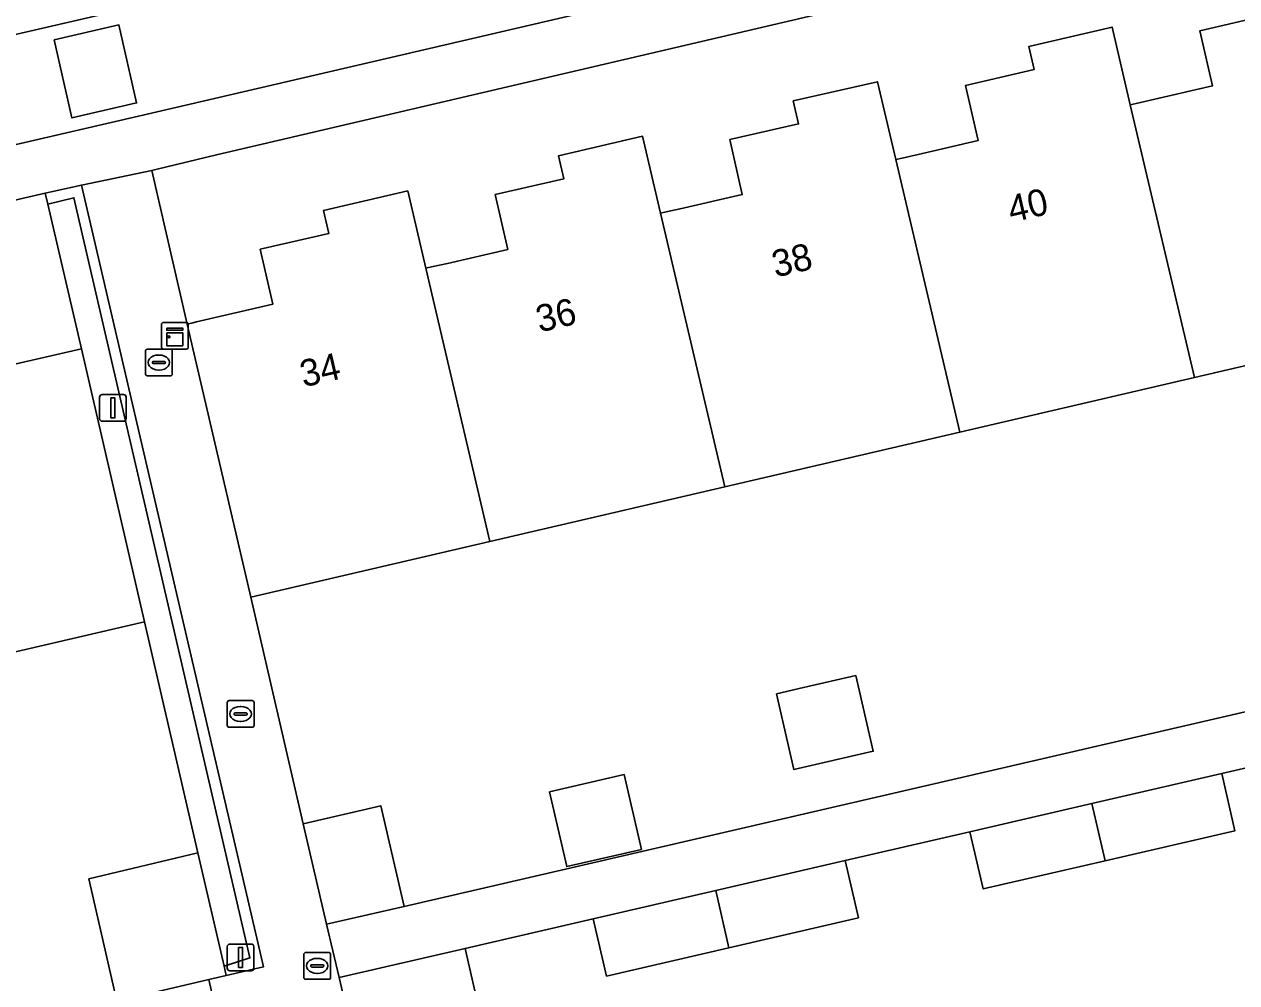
# Model space of a CAD drawing. Extents: x 156412 to 157779, y 382335 to 383768.
# Drawn here: x 156851.95 to 156897.2, y 382800.53 to 382836.3 of the extents above; entities that cross this region are included whole.
import ezdxf

# ---------------------------------------------------------------- set-up
doc = ezdxf.new("R2010")
doc.units = 0
for name, color, linetype in [('IMGEO_Erf', 7, 'Continuous'), ('IMGEO_Groenvoorziening', 7, 'Continuous'), ('IMGEO_Kast', 7, 'Continuous'), ('IMGEO_Kolk', 7, 'Continuous'), ('IMGEO_Lichtmast', 7, 'Continuous'), ('IMGEO_Muur', 7, 'Continuous'), ('IMGEO_Pand', 7, 'Continuous'), ('IMGEO_Pand_nummerreeks', 7, 'Continuous'), ('IMGEO_Rijbaan_lokaal_gesloten', 7, 'Continuous'), ('IMGEO_Rijbaan_lokaal_open', 7, 'Continuous'), ('IMGEO_Rioolput', 7, 'Continuous'), ('IMGEO_Voetpad_open', 7, 'Continuous')]:
    doc.layers.add(name, color=color, linetype=linetype)

msp = doc.modelspace()

# ---------------------------------------------------------------- linework, layer by layer
at = {"layer": 'IMGEO_Erf'}
for points in [[(156927.114, 382847.315), (156859.126, 382831.425), (156856.91, 382830.891), (156856.714, 382830.844), (156858.03, 382825.104), (156858.233, 382825.158), (156858.381, 382825.198), (156861.226, 382825.856), (156860.753, 382827.902), (156863.315, 382828.495), (156863.117, 382829.352), (156866.258, 382830.078), (156866.935, 382827.191), (156867.151, 382827.241), (156867.738, 382827.376), (156869.996, 382827.897), (156869.524, 382829.944), (156872.086, 382830.535), (156871.889, 382831.393), (156875.024, 382832.117), (156875.698, 382829.25), (156875.9, 382829.296), (156876.422, 382829.415), (156878.747, 382829.944), (156878.28, 382831.992), (156880.845, 382832.576), (156880.649, 382833.434), (156883.79, 382834.15), (156884.473, 382831.247), (156884.71, 382831.302), (156885.471, 382831.48), (156887.553, 382831.965), (156887.077, 382834.01), (156889.638, 382834.608), (156889.438, 382835.465), (156892.545, 382836.189), (156893.227, 382833.293), (156893.451, 382833.345), (156894.3, 382833.542), (156896.296, 382834.004), (156895.822, 382836.05), (156898.385, 382836.643)], [(156850.878, 382823.45), (156854.088, 382824.184), (156852.823, 382829.586), (156852.727, 382829.996), (156782.34, 382813.73)], [(156901.237, 382809.4), (156896.638, 382808.337), (156897.131, 382806.203), (156892.289, 382805.084), (156887.738, 382804.033), (156887.245, 382806.167), (156882.588, 382805.091), (156883.082, 382802.956), (156878.25, 382801.84), (156873.679, 382800.784), (156873.186, 382802.919), (156868.402, 382801.813), (156868.894, 382799.682)]]:
    msp.add_lwpolyline(points, dxfattribs=at)
for points in [[(156923.79, 382820.948), (156926.665, 382821.615), (156927.6, 382817.588), (156933.697, 382818.983), (156930.84, 382831.306), (156921.915, 382829.231), (156913.155, 382827.194), (156913.44, 382825.7), (156908.457, 382824.541), (156908.113, 382826.021), (156904.385, 382825.154), (156895.625, 382823.117), (156886.866, 382821.08), (156878.096, 382819.04), (156869.326, 382817.001), (156860.401, 382814.925), (156862.355, 382806.461), (156865.257, 382807.132), (156866.124, 382803.38), (156910.089, 382813.546), (156924.725, 382816.92)], [(156854.352, 382804.41), (156858.429, 382805.383), (156856.435, 382813.996), (156847.542, 382811.941), (156838.763, 382809.913), (156830.005, 382807.89), (156821.243, 382805.866), (156812.469, 382803.839), (156803.704, 382801.814), (156794.934, 382799.788), (156786.03, 382797.749), (156789.002, 382784.941), (156789.092, 382784.551), (156855.404, 382799.852)], [(156880.02, 382811.313), (156881.026, 382811.545), (156882.978, 382811.996), (156883.631, 382809.171), (156880.672, 382808.488)], [(156871.551, 382807.654), (156874.339, 382808.298), (156874.983, 382805.51), (156872.195, 382804.867)]]:
    msp.add_lwpolyline(points, close=True, dxfattribs=at)
at = {"layer": 'IMGEO_Groenvoorziening'}
msp.add_lwpolyline([(156859.404, 382801.15), (156860.37, 382801.457), (156853.8, 382829.822), (156852.823, 382829.586), (156854.088, 382824.184), (156856.435, 382813.996), (156858.429, 382805.383)], close=True, dxfattribs=at)
at = {"layer": 'IMGEO_Kast'}
for p, q in [((156857.069, 382824.248), (156857.069, 382825.089)), ((156857.069, 382825.089), (156857.069, 382824.248)), ((156857.144, 382825.173), (156857.985, 382825.173)), ((156857.985, 382825.173), (156857.144, 382825.173)), ((156858.069, 382825.098), (156858.069, 382824.257)), ((156858.069, 382824.257), (156858.069, 382825.098)), ((156857.994, 382824.173), (156857.153, 382824.173)), ((156857.153, 382824.173), (156857.994, 382824.173))]:
    msp.add_line(p, q, dxfattribs=at)
for points in [[(156857.264, 382824.963), (156857.864, 382824.963), (156857.864, 382824.878), (156857.264, 382824.878), (156857.264, 382824.963)], [(156857.264, 382824.788), (156857.864, 382824.788), (156857.864, 382824.299), (156857.264, 382824.299), (156857.264, 382824.788)]]:
    msp.add_lwpolyline(points, dxfattribs=at)
msp.add_circle((156857.348, 382824.637), 0.0377, dxfattribs=at)
for centre, start, end in [((156857.147, 382825.095), 92.4484, 184.2845), ((156857.147, 382825.095), 92.4484, 184.2845), ((156857.991, 382825.095), 2.4484, 94.2845), ((156857.991, 382825.095), 2.4484, 94.2845), ((156857.147, 382824.251), 182.4484, 274.2845), ((156857.147, 382824.251), 182.4484, 274.2845), ((156857.991, 382824.251), 272.4484, 4.2845), ((156857.991, 382824.251), 272.4484, 4.2845)]:
    msp.add_arc(centre, 0.0779, start, end, dxfattribs=at)
at = {"layer": 'IMGEO_Kolk'}
for p, q in [((156856.47, 382823.25), (156856.47, 382824.102)), ((156856.545, 382824.176), (156857.397, 382824.176)), ((156856.958, 382823.956), (156856.983, 382823.956)), ((156857.471, 382824.102), (156857.471, 382823.25)), ((156856.729, 382823.67), (156856.729, 382823.682)), ((156857.167, 382823.633), (156856.769, 382823.633)), ((156856.772, 382823.719), (156857.17, 382823.719)), ((156857.213, 382823.682), (156857.213, 382823.67)), ((156857.397, 382823.176), (156856.545, 382823.176)), ((156856.981, 382823.396), (156856.956, 382823.396)), ((156859.522, 382810.138), (156859.522, 382810.99)), ((156859.597, 382811.064), (156860.449, 382811.064)), ((156860.01, 382810.844), (156860.035, 382810.844)), ((156860.523, 382810.99), (156860.523, 382810.138)), ((156859.781, 382810.558), (156859.781, 382810.57)), ((156860.219, 382810.521), (156859.821, 382810.521)), ((156859.824, 382810.607), (156860.222, 382810.607)), ((156860.265, 382810.57), (156860.265, 382810.558)), ((156860.449, 382810.064), (156859.597, 382810.064)), ((156860.033, 382810.284), (156860.008, 382810.284))]:
    msp.add_line(p, q, dxfattribs=at)
for points in [[(156856.47, 382823.25), (156856.47, 382824.102)], [(156856.545, 382824.176), (156857.397, 382824.176)], [(156857.471, 382824.102), (156857.471, 382823.25)], [(156857.397, 382823.176), (156856.545, 382823.176)], [(156859.522, 382810.138), (156859.522, 382810.99)], [(156859.597, 382811.064), (156860.449, 382811.064)], [(156860.523, 382810.99), (156860.523, 382810.138)], [(156860.449, 382810.064), (156859.597, 382810.064)]]:
    msp.add_lwpolyline(points, dxfattribs=at)
for centre, radius, start, end in [((156856.547, 382824.1), 0.0765, 91.552, 178.448), ((156856.547, 382824.1), 0.0765, 91.552, 178.448), ((156857.395, 382824.1), 0.0765, 1.552, 88.448), ((156857.395, 382824.1), 0.0765, 1.552, 88.448), ((156856.769, 382823.679), 0.0403, 85.8775, 175.7526), ((156856.766, 382823.669), 0.0366, 178.938, 274.7102), ((156857.17, 382823.676), 0.043, 264.8664, 352.4533), ((156857.174, 382823.681), 0.0386, 1.7309, 96.639), ((156856.547, 382823.252), 0.0765, 181.552, 268.448), ((156856.547, 382823.252), 0.0765, 181.552, 268.448), ((156857.395, 382823.252), 0.0765, 271.552, 358.448), ((156857.395, 382823.252), 0.0765, 271.552, 358.448), ((156859.599, 382810.988), 0.0765, 91.552, 178.448), ((156859.599, 382810.988), 0.0765, 91.552, 178.448), ((156860.447, 382810.988), 0.0765, 1.552, 88.448), ((156860.447, 382810.988), 0.0765, 1.552, 88.448), ((156859.821, 382810.567), 0.0403, 85.8775, 175.7526), ((156859.818, 382810.557), 0.0366, 178.938, 274.7102), ((156860.222, 382810.564), 0.043, 264.8664, 352.4533), ((156860.226, 382810.569), 0.0386, 1.7309, 96.639), ((156859.599, 382810.14), 0.0765, 181.552, 268.448), ((156859.599, 382810.14), 0.0765, 181.552, 268.448), ((156860.447, 382810.14), 0.0765, 271.552, 358.448), ((156860.447, 382810.14), 0.0765, 271.552, 358.448)]:
    msp.add_arc(centre, radius, start, end, dxfattribs=at)
for centre, major_axis, ratio, start_param, end_param in [((156856.957, 382823.676), (-0.387, 0.002), 0.722429, 4.712389, 7.853982), ((156856.982, 382823.676), (-0.39, 0.002), 0.717154, 1.570796, 4.712389), ((156860.009, 382810.564), (-0.387, 0.002), 0.722429, 4.712389, 7.853982), ((156860.034, 382810.564), (-0.39, 0.002), 0.717154, 1.570796, 4.712389)]:
    msp.add_ellipse(centre, major_axis=major_axis, ratio=ratio, start_param=start_param, end_param=end_param, dxfattribs=at)
at = {"layer": 'IMGEO_Lichtmast'}
for p, q in [((156854.761, 382821.582), (156854.761, 382822.382)), ((156854.761, 382822.382), (156854.761, 382821.582)), ((156854.861, 382822.482), (156855.651, 382822.482)), ((156855.651, 382822.482), (156854.861, 382822.482)), ((156855.751, 382822.382), (156855.751, 382821.582)), ((156855.751, 382821.582), (156855.751, 382822.382)), ((156855.651, 382821.482), (156854.861, 382821.482)), ((156854.861, 382821.482), (156855.651, 382821.482)), ((156859.525, 382801.079), (156859.525, 382801.879)), ((156859.525, 382801.879), (156859.525, 382801.079)), ((156859.625, 382801.979), (156860.415, 382801.979)), ((156860.415, 382801.979), (156859.625, 382801.979)), ((156860.515, 382801.879), (156860.515, 382801.079)), ((156860.515, 382801.079), (156860.515, 382801.879)), ((156860.415, 382800.979), (156859.625, 382800.979)), ((156859.625, 382800.979), (156860.415, 382800.979))]:
    msp.add_line(p, q, dxfattribs=at)
for points in [[(156855.181, 382822.357), (156855.331, 382822.357), (156855.331, 382821.607), (156855.181, 382821.607), (156855.181, 382822.357)], [(156859.945, 382801.854), (156860.095, 382801.854), (156860.095, 382801.104), (156859.945, 382801.104), (156859.945, 382801.854)]]:
    msp.add_lwpolyline(points, dxfattribs=at)
for centre, start, end in [((156854.861, 382822.382), 90, 180), ((156854.861, 382822.382), 90, 180), ((156855.651, 382822.382), 0, 90), ((156855.651, 382822.382), 360, 90), ((156854.861, 382821.582), 180, 270), ((156854.861, 382821.582), 180, 270), ((156855.651, 382821.582), 270, 0), ((156855.651, 382821.582), 270, 0), ((156859.625, 382801.879), 90, 180), ((156859.625, 382801.879), 90, 180), ((156860.415, 382801.879), 0, 90), ((156860.415, 382801.879), 360, 90), ((156859.625, 382801.079), 180, 270), ((156859.625, 382801.079), 180, 270), ((156860.415, 382801.079), 270, 0), ((156860.415, 382801.079), 270, 0)]:
    msp.add_arc(centre, 0.1, start, end, dxfattribs=at)
at = {"layer": 'IMGEO_Muur'}
msp.add_lwpolyline([(156854.08, 382830.294), (156852.727, 382829.996), (156852.823, 382829.586), (156853.8, 382829.822), (156860.37, 382801.457), (156859.404, 382801.15), (156859.483, 382800.805), (156860.871, 382801.126)], close=True, dxfattribs=at)
for points in [[(156862.355, 382806.461), (156860.401, 382814.925)], [(156856.435, 382813.996), (156858.429, 382805.383)]]:
    msp.add_lwpolyline(points, dxfattribs=at)
at = {"layer": 'IMGEO_Pand'}
for points in [[(156901.988, 382835.311), (156901.301, 382838.221), (156898.186, 382837.5), (156898.385, 382836.643), (156895.822, 382836.05), (156896.296, 382834.004), (156894.3, 382833.542), (156893.451, 382833.345), (156893.227, 382833.293), (156895.625, 382823.117), (156904.385, 382825.154)], [(156893.227, 382833.293), (156892.545, 382836.189), (156889.438, 382835.465), (156889.638, 382834.608), (156887.077, 382834.01), (156887.553, 382831.965), (156885.471, 382831.48), (156884.71, 382831.302), (156884.473, 382831.247), (156886.866, 382821.08), (156895.625, 382823.117)], [(156884.473, 382831.247), (156883.79, 382834.15), (156880.649, 382833.434), (156880.845, 382832.576), (156878.28, 382831.992), (156878.747, 382829.944), (156876.422, 382829.415), (156875.9, 382829.296), (156875.698, 382829.25), (156878.096, 382819.04), (156886.866, 382821.08)], [(156875.698, 382829.25), (156875.024, 382832.117), (156871.889, 382831.393), (156872.086, 382830.535), (156869.524, 382829.944), (156869.996, 382827.897), (156867.738, 382827.376), (156867.151, 382827.241), (156866.935, 382827.191), (156869.326, 382817.001), (156878.096, 382819.04)], [(156866.935, 382827.191), (156866.258, 382830.078), (156863.117, 382829.352), (156863.315, 382828.495), (156860.753, 382827.902), (156861.226, 382825.856), (156858.381, 382825.198), (156858.233, 382825.158), (156858.03, 382825.104), (156860.401, 382814.925), (156869.326, 382817.001)], [(156844.51, 382825.019), (156847.542, 382811.941), (156856.435, 382813.996), (156854.088, 382824.184), (156850.878, 382823.45), (156850.4, 382825.479), (156847.859, 382824.88), (156847.662, 382825.748)], [(156880.02, 382811.313), (156880.672, 382808.488), (156883.631, 382809.171), (156882.978, 382811.996), (156881.026, 382811.545)], [(156871.551, 382807.654), (156872.195, 382804.867), (156874.983, 382805.51), (156874.339, 382808.298)], [(156892.289, 382805.084), (156897.131, 382806.203), (156896.638, 382808.337), (156891.793, 382807.218)], [(156892.289, 382805.084), (156891.793, 382807.218), (156887.245, 382806.167), (156887.738, 382804.033)], [(156862.355, 382806.461), (156863.234, 382802.713), (156866.124, 382803.38), (156865.257, 382807.132)], [(156859.404, 382801.15), (156858.429, 382805.383), (156854.352, 382804.41), (156855.404, 382799.852), (156858.834, 382800.653), (156859.483, 382800.805)], [(156878.25, 382801.84), (156883.082, 382802.956), (156882.588, 382805.091), (156877.753, 382803.974)], [(156878.25, 382801.84), (156877.753, 382803.974), (156873.186, 382802.919), (156873.679, 382800.784)], [(156863.704, 382800.728), (156864.203, 382798.597), (156868.894, 382799.682), (156868.402, 382801.813)]]:
    msp.add_lwpolyline(points, close=True, dxfattribs=at)
at = {"layer": 'IMGEO_Rijbaan_lokaal_gesloten'}
for points in [[(156925.817, 382853.068), (156855.39, 382836.785), (156816.178, 382827.739), (156776.982, 382818.697), (156706.623, 382802.451), (156704.67, 382802.003), (156705.372, 382798.026), (156707.336, 382798.509), (156707.464, 382798.538), (156780.281, 382815.295), (156817.084, 382823.811), (156856.378, 382832.904)], [(156856.378, 382832.904), (156923.197, 382848.454), (156926.664, 382849.268), (156926.769, 382849.293)]]:
    msp.add_lwpolyline(points, dxfattribs=at)
msp.add_lwpolyline([(156853.064, 382835.711), (156855.479, 382836.274), (156856.141, 382833.365), (156853.725, 382832.8)], close=True, dxfattribs=at)
at = {"layer": 'IMGEO_Rijbaan_lokaal_open'}
msp.add_lwpolyline([(156704.67, 382802.003), (156706.623, 382802.451), (156776.982, 382818.697), (156816.178, 382827.739), (156855.39, 382836.785), (156925.817, 382853.068)], dxfattribs=at)
msp.add_lwpolyline([(156853.725, 382832.8), (156856.141, 382833.365), (156855.479, 382836.274), (156853.064, 382835.711)], close=True, dxfattribs=at)
at = {"layer": 'IMGEO_Rioolput'}
for p, q in [((156862.381, 382800.737), (156862.381, 382801.589)), ((156862.456, 382801.663), (156863.308, 382801.663)), ((156862.869, 382801.443), (156862.894, 382801.443)), ((156863.382, 382801.589), (156863.382, 382800.737)), ((156862.64, 382801.157), (156862.64, 382801.169)), ((156863.078, 382801.12), (156862.68, 382801.12)), ((156862.683, 382801.206), (156863.081, 382801.206)), ((156862.892, 382800.883), (156862.867, 382800.883)), ((156863.124, 382801.169), (156863.124, 382801.157)), ((156863.308, 382800.663), (156862.456, 382800.663))]:
    msp.add_line(p, q, dxfattribs=at)
for points in [[(156862.381, 382800.737), (156862.381, 382801.589)], [(156862.456, 382801.663), (156863.308, 382801.663)], [(156863.382, 382801.589), (156863.382, 382800.737)], [(156863.308, 382800.663), (156862.456, 382800.663)]]:
    msp.add_lwpolyline(points, dxfattribs=at)
for centre, radius, start, end in [((156862.458, 382801.587), 0.0765, 91.552, 178.448), ((156862.458, 382801.587), 0.0765, 91.552, 178.448), ((156863.306, 382801.587), 0.0765, 1.552, 88.448), ((156863.306, 382801.587), 0.0765, 1.552, 88.448), ((156862.68, 382801.166), 0.0403, 85.8775, 175.7526), ((156862.677, 382801.156), 0.0366, 178.938, 274.7102), ((156863.081, 382801.163), 0.043, 264.8664, 352.4533), ((156863.085, 382801.168), 0.0386, 1.7309, 96.639), ((156862.458, 382800.739), 0.0765, 181.552, 268.448), ((156862.458, 382800.739), 0.0765, 181.552, 268.448), ((156863.306, 382800.739), 0.0765, 271.552, 358.448), ((156863.306, 382800.739), 0.0765, 271.552, 358.448)]:
    msp.add_arc(centre, radius, start, end, dxfattribs=at)
for centre, major_axis, ratio, start_param, end_param in [((156862.868, 382801.163), (-0.387, 0.002), 0.722429, 4.712389, 7.853982), ((156862.893, 382801.163), (-0.39, 0.002), 0.717154, 1.570796, 4.712389)]:
    msp.add_ellipse(centre, major_axis=major_axis, ratio=ratio, start_param=start_param, end_param=end_param, dxfattribs=at)
at = {"layer": 'IMGEO_Voetpad_open'}
for points in [[(156852.727, 382829.996), (156854.08, 382830.294), (156856.714, 382830.844), (156856.91, 382830.891), (156859.126, 382831.425), (156927.114, 382847.315), (156926.664, 382849.268), (156923.197, 382848.454), (156856.378, 382832.904), (156817.084, 382823.811), (156780.281, 382815.295), (156707.464, 382798.538), (156707.908, 382796.596), (156778.432, 382812.831), (156780.962, 382813.412), (156782.34, 382813.73)], [(156860.401, 382814.925), (156858.03, 382825.104), (156856.714, 382830.844), (156854.08, 382830.294), (156860.871, 382801.126), (156859.483, 382800.805), (156858.834, 382800.653), (156859.29, 382798.675), (156859.972, 382798.832), (156861.369, 382799.171), (156866.975, 382774.768), (156869.58, 382775.359), (156868.89, 382778.342), (156866.184, 382790.023), (156864.203, 382798.597), (156863.704, 382800.728), (156863.234, 382802.713), (156862.355, 382806.461)], [(156901.237, 382809.4), (156905.843, 382810.464), (156910.611, 382811.566), (156915.259, 382812.64), (156919.855, 382813.702), (156924.651, 382814.81), (156929.454, 382815.919), (156934.158, 382817.006), (156933.697, 382818.983), (156927.6, 382817.588), (156924.725, 382816.92), (156910.089, 382813.546), (156866.124, 382803.38), (156863.234, 382802.713), (156863.704, 382800.728), (156868.402, 382801.813), (156873.186, 382802.919), (156877.753, 382803.974), (156882.588, 382805.091), (156887.245, 382806.167), (156891.793, 382807.218), (156896.638, 382808.337)], [(156803.731, 382785.854), (156810.743, 382787.473), (156817.756, 382789.091), (156824.77, 382790.709), (156831.783, 382792.327), (156838.796, 382793.946), (156845.81, 382795.564), (156852.823, 382797.182), (156859.29, 382798.675), (156858.834, 382800.653), (156855.404, 382799.852), (156789.092, 382784.551), (156787.72, 382784.234), (156788.095, 382782.246), (156789.549, 382782.582), (156796.717, 382784.236)]]:
    msp.add_lwpolyline(points, close=True, dxfattribs=at)

# ---------------------------------------------------------------- texts
at = {"layer": 'IMGEO_Pand_nummerreeks'}
for s, p in [('40', (156888.787, 382828.892)), ('38', (156879.983, 382826.843)), ('36', (156871.176, 382824.794)), ('34', (156862.371, 382822.746))]:
    msp.add_text(s, height=1, rotation=13.0978, dxfattribs=at).set_placement(p)

doc.saveas('drawing.dxf')
